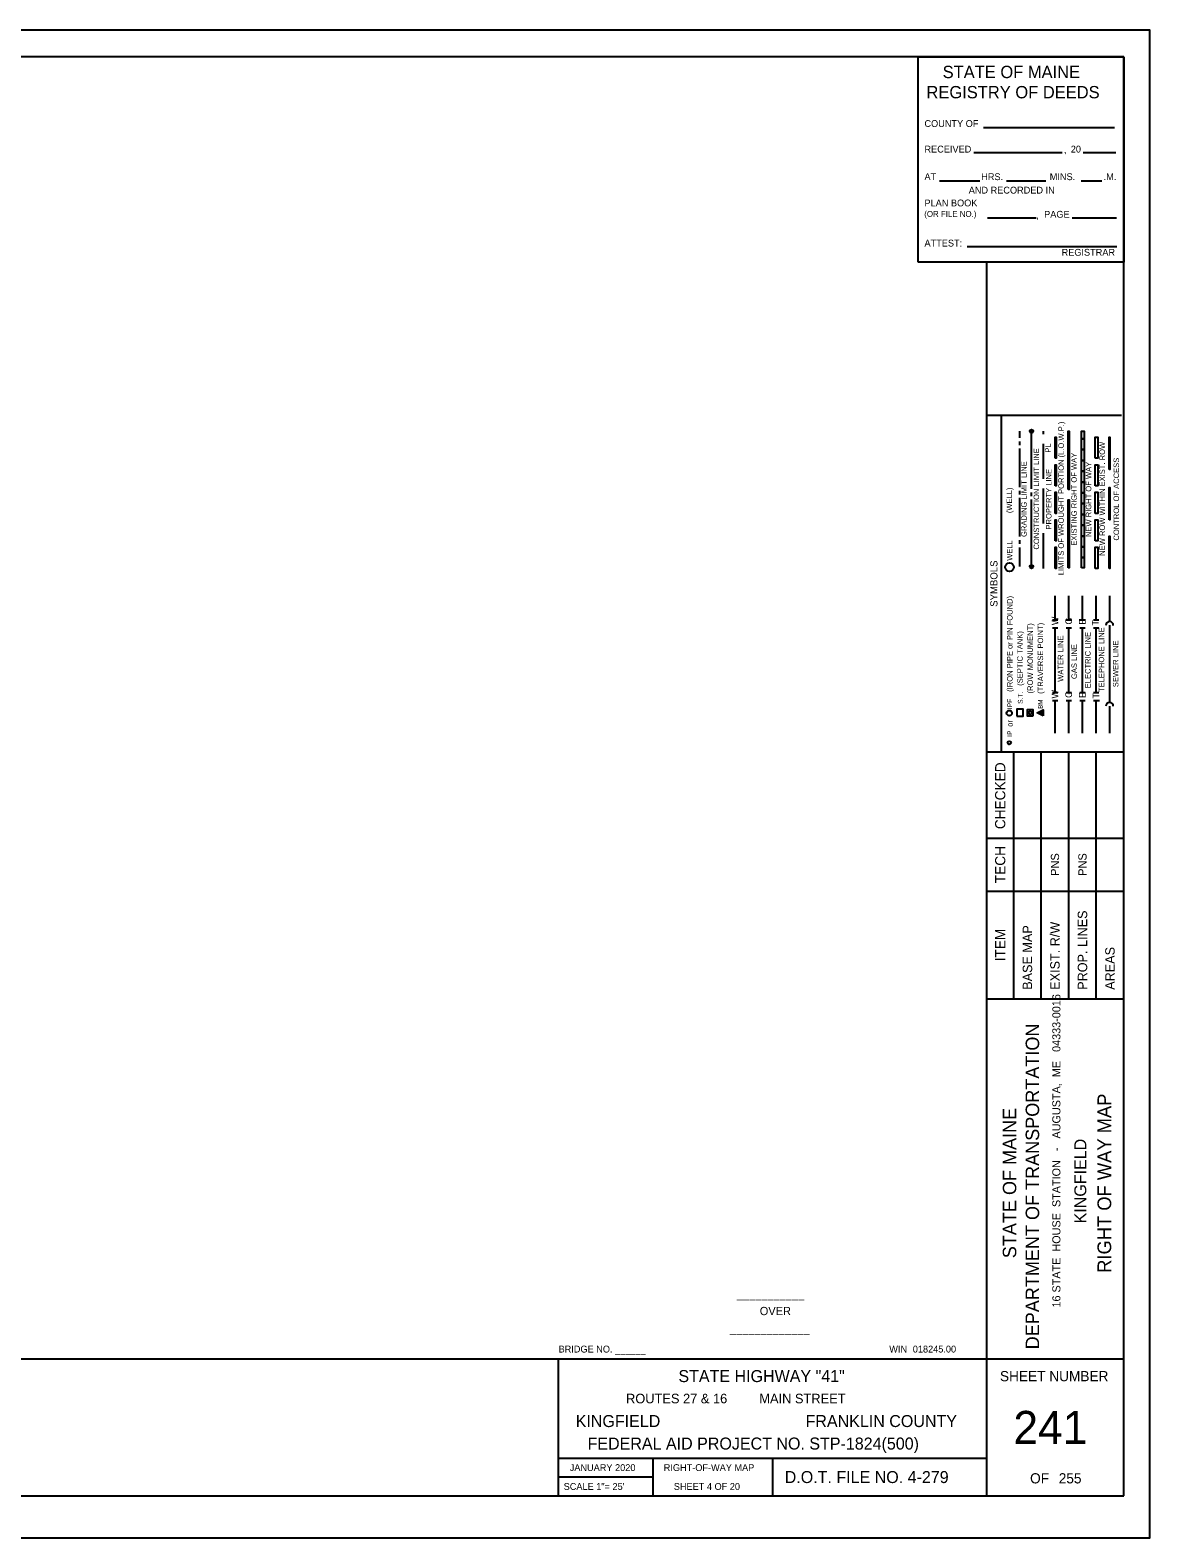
# Model space of a CAD drawing. Extents: x -415 to 435, y -303 to 247.
# Drawn here: x 26 to 435, y -303 to 247 of the extents above; entities that cross this region are included whole.
import ezdxf

# ---------------------------------------------------------------- set-up
doc = ezdxf.new("R2010")
doc.units = 0
for name, color, linetype in [('Border', 7, 'Continuous'), ('BRIDGE_TITLE', 7, 'Continuous'), ('HIGHWAY_TITLE', 7, 'Continuous'), ('PLOT BOUNDARY', 7, 'Continuous'), ('PRPTY SETUPS', 7, 'Continuous')]:
    doc.layers.add(name, color=color, linetype=linetype)

msp = doc.modelspace()

# ---------------------------------------------------------------- linework, layer by layer
at = {"layer": 'Border'}
for p, q in [((425, 237.5), (-375, 237.5)), ((425, -287.49), (425, 237.5)), ((375, -287.5), (375, 162.52)), ((375, 106.81), (424.21, 106.81)), ((380.25, 106.81), (380.25, -16.1)), ((387.03, 98.49), (387.03, 100.86)), ((391.35, 79.88), (391.35, 100.24)), ((395.67, 99.88), (395.67, 100.86)), ((387.03, 95.86), (387.03, 97.18)), ((387.03, 87.51), (387.03, 94.55)), ((395.67, 83.54), (395.67, 96.34)), ((387.03, 80.47), (387.03, 87.51)), ((387.03, 77.85), (387.03, 79.16)), ((391.35, 77.25), (391.35, 78.57)), ((395.67, 67.2), (395.67, 80)), ((387.03, 69.5), (387.03, 76.54)), ((391.35, 52.11), (391.35, 75.94)), ((387.03, 62.46), (387.03, 69.5)), ((387.03, 59.84), (387.03, 61.15)), ((395.67, 50.86), (395.67, 63.66)), ((387.03, 51.49), (387.03, 58.53)), ((399.99, 32.13), (399.99, 40.79)), ((404.97, 32.13), (404.97, 40.79)), ((409.94, 32.13), (409.94, 40.79)), ((414.92, 32.13), (414.92, 40.79)), ((419.9, 31.54), (419.9, 40.79)), ((399.01, 32.13), (400.98, 32.13)), ((399.01, 29.18), (400.98, 29.18)), ((399.99, 5.56), (399.99, 29.18)), ((403.98, 32.13), (405.95, 32.13)), ((403.98, 29.18), (405.95, 29.18)), ((404.97, 17.37), (404.97, 29.18)), ((408.96, 32.13), (410.93, 32.13)), ((408.96, 29.18), (410.93, 29.18)), ((409.94, 17.37), (409.94, 29.18)), ((413.94, 32.13), (415.9, 32.13)), ((413.94, 29.18), (415.9, 29.18)), ((414.92, 17.37), (414.92, 29.18)), ((419.9, 20.32), (419.9, 30.16)), ((404.97, 5.56), (404.97, 17.37)), ((409.94, 5.56), (409.94, 17.37)), ((414.92, 5.56), (414.92, 17.37)), ((419.9, 2.01), (419.9, 20.32)), ((399.01, 5.56), (400.98, 5.56)), ((403.98, 5.56), (405.95, 5.56)), ((408.96, 5.56), (410.93, 5.56)), ((413.94, 5.56), (415.9, 5.56)), ((399.01, 2.61), (400.98, 2.61)), ((399.99, -9.21), (399.99, 2.61)), ((403.98, 2.61), (405.95, 2.61)), ((404.97, -9.21), (404.97, 2.61)), ((408.96, 2.61), (410.93, 2.61)), ((409.94, -9.21), (409.94, 2.61)), ((413.94, 2.61), (416.1, 2.61)), ((414.92, -9.21), (414.92, 2.61)), ((419.9, -9.21), (419.9, 0.64)), ((375, -16.1), (425, -16.1)), ((384.84, -106.22), (384.84, -16.1)), ((394.88, -106.22), (394.88, -16.1)), ((404.92, -106.22), (404.92, -16.1)), ((414.96, -106.22), (414.96, -16.1)), ((375, -47.6), (425, -47.6)), ((375, -66.94), (425, -66.94)), ((375, -106.22), (425, -106.22)), ((-375, -237.49), (425, -237.49)), ((218.75, -287.5), (218.75, -237.49)), ((218.75, -273.75), (375, -273.75)), ((253.12, -273.75), (253.12, -287.5)), ((296.87, -273.75), (296.87, -287.5)), ((253.12, -280.62), (218.75, -280.62)), ((-375, -287.5), (425, -287.5))]:
    msp.add_line(p, q, dxfattribs=at)
for points in [[(404.71, 79.6), (404.71, 100.86), (405.1, 100.86), (405.1, 79.6)], [(409.62, 98.11), (409.62, 100.86), (410.6, 100.86), (410.6, 98.11)], [(399.99, 91.02), (399.99, 98.7), (400.39, 98.7), (400.39, 91.02)], [(409.62, 94.17), (409.62, 98.11), (410.6, 98.11), (410.6, 94.17)], [(409.62, 90.23), (409.62, 94.17), (410.6, 94.17), (410.6, 90.23)], [(414.59, 91.02), (414.59, 98.7), (415.58, 98.7), (415.58, 91.02)], [(419.7, 86.89), (419.7, 98.7), (419.9, 98.7), (419.9, 86.89)], [(399.99, 80.98), (399.99, 88.66), (400.39, 88.66), (400.39, 80.98)], [(409.62, 86.3), (409.62, 90.23), (410.6, 90.23), (410.6, 86.3)], [(414.59, 80.98), (414.59, 88.66), (415.58, 88.66), (415.58, 80.98)], [(409.62, 82.36), (409.62, 86.3), (410.6, 86.3), (410.6, 82.36)], [(399.99, 70.94), (399.99, 78.62), (400.39, 78.62), (400.39, 70.94)], [(409.62, 78.42), (409.62, 82.36), (410.6, 82.36), (410.6, 78.42)], [(409.62, 74.48), (409.62, 78.42), (410.6, 78.42), (410.6, 74.48)], [(414.59, 70.94), (414.59, 78.62), (415.58, 78.62), (415.58, 70.94)], [(419.7, 68.58), (419.7, 80.39), (419.9, 80.39), (419.9, 68.58)], [(404.71, 51.06), (404.71, 75.86), (405.1, 75.86), (405.1, 51.06)], [(409.62, 70.55), (409.62, 74.48), (410.6, 74.48), (410.6, 70.55)], [(399.99, 60.9), (399.99, 68.58), (400.39, 68.58), (400.39, 60.9)], [(409.62, 66.61), (409.62, 70.55), (410.6, 70.55), (410.6, 66.61)], [(409.62, 62.67), (409.62, 66.61), (410.6, 66.61), (410.6, 62.67)], [(414.59, 60.9), (414.59, 68.58), (415.58, 68.58), (415.58, 60.9)], [(409.62, 58.74), (409.62, 62.67), (410.6, 62.67), (410.6, 58.74)], [(419.7, 50.86), (419.7, 62.67), (419.9, 62.67), (419.9, 50.86)], [(399.99, 50.86), (399.99, 58.54), (400.39, 58.54), (400.39, 50.86)], [(409.62, 54.8), (409.62, 58.74), (410.6, 58.74), (410.6, 54.8)], [(414.59, 50.86), (414.59, 58.54), (415.58, 58.54), (415.58, 50.86)], [(409.62, 51.06), (409.62, 54.8), (410.6, 54.8), (410.6, 51.06)]]:
    msp.add_lwpolyline(points, close=True, dxfattribs=at)
for points in [[(385.95, -3.1), (388.31, -3.1), (388.31, -0.54), (385.95, -0.54), (385.95, -3.1)], [(391.98, -2.95), (391.98, -0.7), (389.73, -0.7), (389.73, -2.95), (391.98, -2.95)], [(395.54, -2.89), (393.44, -1.83), (395.54, -0.78), (395.54, -2.89)]]:
    msp.add_lwpolyline(points, dxfattribs=at)
for centre, radius in [((391.35, 100.86), 0.625), ((391.35, 100.86), 0.15), ((391.35, 100.86), 0.05), ((383.29, 51.3), 1.57), ((391.35, 51.49), 0.625), ((391.35, 51.49), 0.15), ((391.35, 51.49), 0.05), ((383.24, -1.91), 0.966), ((390.86, -1.82), 0.563), ((394.86, -1.82), 0.281), ((383.24, -12.74), 0.625)]:
    msp.add_circle(centre, radius, dxfattribs=at)
for centre in [(419.84, 30.08), (419.84, 0.56)]:
    msp.add_arc(centre, 1.35, 0, 180, dxfattribs=at)
at = {"layer": 'PLOT BOUNDARY'}
msp.add_lwpolyline([(-415.47, -302.8), (434.53, -302.8), (434.53, 247.2), (-415.47, 247.2)], close=True, dxfattribs=at)
at = {"layer": 'PRPTY SETUPS'}
for p, q in [((350.02, 237.5), (425, 237.5)), ((350.02, 162.52), (350.02, 237.5)), ((425, 237.5), (425, 162.52)), ((373.83, 211.74), (421.57, 211.74)), ((370.29, 202.57), (402.52, 202.57)), ((410.24, 202.57), (422.1, 202.57)), ((357.72, 192.29), (372.5, 192.29)), ((382.25, 192.29), (396.61, 192.29)), ((409.44, 192.29), (417, 192.29)), ((375.32, 178.78), (393.03, 178.78)), ((406.16, 178.78), (422.34, 178.78)), ((367.9, 168.33), (422.43, 168.33)), ((425, 162.52), (350.02, 162.52))]:
    msp.add_line(p, q, dxfattribs=at)

# ---------------------------------------------------------------- texts
at = {"layer": 'Border'}
for s, height, rotation, p in [('LIMITS OF WROUGHT PORTION (L.O.W.P.)', 1.9996, 90, (403.14, 48.4)), ('PL', 2, 90, (398.35, 93.09)), ('NEW ROW WITHIN EXIST. ROW', 1.9996, 90, (418.14, 55.45)), ('GRADING LIMIT LINE', 1.9996, 90, (389.59, 62.32)), ('CONSTRUCTION LIMIT LINE', 1.9996, 90, (394.11, 57.72)), ('EXISTING RIGHT OF WAY', 1.9996, 90, (407.86, 59.13)), ('NEW RIGHT OF WAY', 1.9996, 90, (413.16, 62.28)), ('CONTROL OF ACCESS', 1.9996, 90, (423.29, 61)), ('PROPERTY LINE', 1.9996, 90, (398.63, 65.04)), ('(WELL)', 2, 90, (384.23, 71.01)), ('WELL', 1.969, 90, (384.36, 53.66)), ('SYMBOLS', 2.614, 90, (378.93, 36.84)), ('(IRON PIPE or PIN FOUND)', 1.9996, 90, (384.41, 5.83)), ('W', 2.46, 90, (401.17, 30.16)), ('(ROW MONUMENT)', 1.9996, 90, (391.85, 5.23)), ('(TRAVERSE POINT)', 1.9996, 90, (395.58, 5.08)), ('G', 2.46, 90, (406.15, 30.36)), ('E', 2.46, 90, (411.13, 30.36)), ('T', 2.46, 90, (415.9, 29.97)), ('TELEPHONE LINE', 1.9996, 90, (417.87, 5.75)), ('(SEPTIC TANK)', 1.9996, 90, (388.13, 8.02)), ('WATER LINE', 2, 90, (402.95, 9.5)), ('GAS LINE', 2, 90, (407.92, 10.48)), ('ELECTRIC LINE', 1.9996, 90, (412.9, 7.13)), ('SEWER LINE', 2, 90, (423.05, 7.53)), ('W', 2.46, 90, (401.17, 3.39)), ('G', 2.46, 90, (406.15, 3.59)), ('E', 2.46, 90, (411.13, 3.59)), ('IPF', 1.749, 90, (384.28, -0.48)), ('S.T.', 1.749, 90, (388.12, 1.42)), ('BM', 1.641, 90, (395.4, -0.38)), ('T', 2.46, 90, (416.1, 3.39)), ('or', 2, 90, (384.47, -6.92)), ('IP', 1.749, 90, (384.28, -10.58)), ('CHECKED', 3.726, 90, (381.78, -44.27)), ('TECH', 3.726, 90, (381.78, -63.99)), ('PROP. LINES', 3.4449, 90, (411.66, -102.87)), ('ITEM', 3.726, 90, (381.78, -92.49)), ('BASE MAP', 3.445, 90, (391.58, -102.87)), ('EXIST. R/W', 3.445, 90, (401.62, -102.87)), ('AREAS', 3.445, 90, (421.7, -102.87)), ('16 STATE  HOUSE  STATION   -   AUGUSTA,  ME   04333-0016', 2.9528, 90, (401.89, -218.78)), ('DEPARTMENT OF TRANSPORTATION', 4.9217, 90, (394.13, -234.02)), ('RIGHT OF WAY MAP', 4.9996, 90, (420.42, -206.11)), ('STATE OF MAINE', 4.9217, 90, (385.79, -200.78)), ('D.O.T. FILE NO. 4-279', 4.375, 360, (301.28, -282.81))]:
    msp.add_text(s, height=height, rotation=rotation, dxfattribs=at).set_placement(p)
for s, height, p in [('SHEET NUMBER', 3.7264, (379.83, -245.67)), ('241', 12.097, (384.73, -268.59)), ('OF', 3.726, (390.83, -282.94)), ('255', 3.726, (401.28, -282.94))]:
    msp.add_text(s, height=height, dxfattribs=at).set_placement(p)
at = {"layer": 'BRIDGE_TITLE'}
for s, height, p in [('___________', 3, (283.84, -215.3)), ('OVER', 3, (292.18, -221.55)), ('_____________', 3, (281.29, -227.8)), ('BRIDGE NO. ______', 2.5, (218.75, -235.19))]:
    msp.add_text(s, height=height, dxfattribs=at).set_placement(p)
at = {"layer": 'HIGHWAY_TITLE'}
for s, height, rotation, p in [('PNS', 3, 90, (401.4, -61.3)), ('PNS', 3, 90, (411.44, -61.3)), ('KINGFIELD', 4.375, 90, (411.35, -188.1)), ('SCALE 1"= 25\'', 2.5, 360, (220.61, -285.31))]:
    msp.add_text(s, height=height, rotation=rotation, dxfattribs=at).set_placement(p)
for s, height, p in [('WIN', 2.5, (339.44, -235.19)), ('018245.00', 2.5, (348.02, -235.19)), ('STATE HIGHWAY "41"', 4.375, (262.49, -245.97)), ('ROUTES 27 & 16         MAIN STREET', 3.5, (243.37, -253.73)), ('KINGFIELD', 4.375, (225, -262.38)), ('FRANKLIN COUNTY', 4.375, (308.88, -262.38)), ('FEDERAL AID PROJECT NO. STP-1824(500)', 4.375, (229.33, -270.58)), ('JANUARY 2020', 2.5, (222.83, -278.43)), ('RIGHT-OF-WAY MAP', 2.5, (257.13, -278.43)), ('SHEET 4 OF 20', 2.5, (260.81, -285.31))]:
    msp.add_text(s, height=height, dxfattribs=at).set_placement(p)
at = {"layer": 'PRPTY SETUPS'}
for s, height, p in [('STATE OF MAINE', 4.5, (358.92, 229.71)), ('REGISTRY OF DEEDS', 4.5, (353.01, 222.33)), ('COUNTY OF', 2.5, (352.28, 211.89)), ('RECEIVED', 2.5, (352.28, 202.55)), ('20', 2.5, (405.68, 202.55)), (',', 2.61, (403.14, 202.33)), ('AT', 2.5, (352.28, 192.49)), ('HRS.', 2.5, (372.99, 192.49)), ('MINS.', 2.5, (398, 192.49)), ('.M.', 2.5, (417.67, 192.49)), ('AND RECORDED IN', 2.5, (368.43, 187.59)), ('PLAN BOOK ', 2.5, (352.28, 182.91)), ('(OR FILE NO.)', 2.1531, (352.21, 179.09)), (',', 2.61, (393.08, 178.45)), ('PAGE', 2.5, (395.95, 178.78)), ('ATTEST:', 2.5, (352.28, 168.27)), ('REGISTRAR', 2.5, (402.33, 164.91))]:
    msp.add_text(s, height=height, dxfattribs=at).set_placement(p)

doc.saveas('drawing.dxf')
